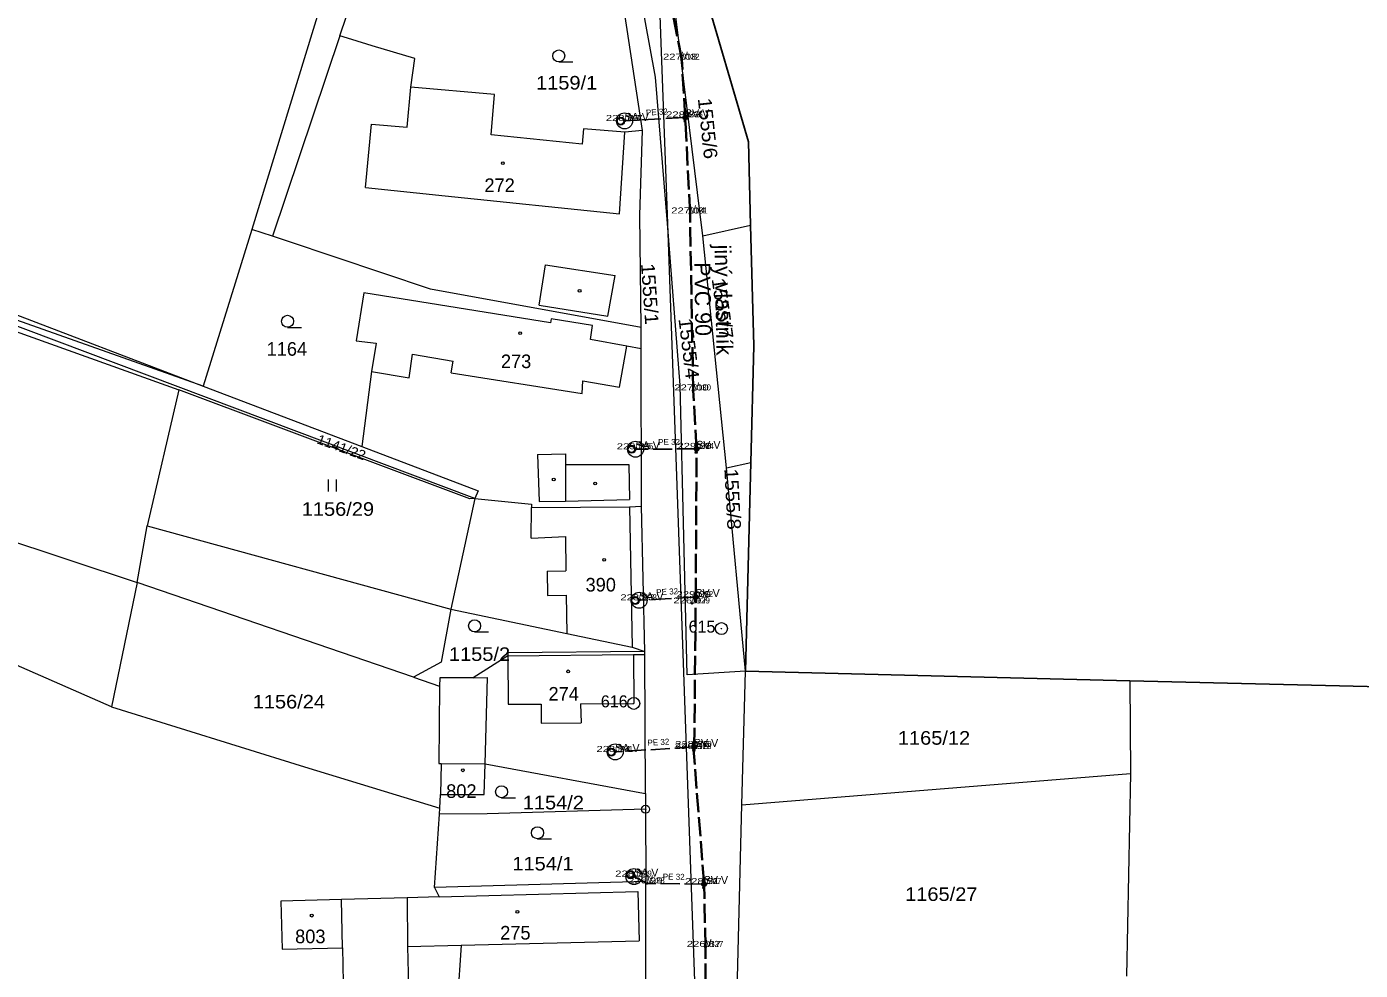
# Model space of a CAD drawing. Extents: x -686207 to -681951, y -1020493 to -1017811.
# Drawn here: x -684335.4 to -684168.7, y -1019065.6 to -1018947.7 of the extents above; entities that cross this region are included whole.
import ezdxf
from ezdxf.enums import TextEntityAlignment as Align

# ---------------------------------------------------------------- set-up
doc = ezdxf.new("R2010")
doc.units = 0
doc.header["$LTSCALE"] = 0.4
doc.header["$PDMODE"] = 32
doc.header["$PDSIZE"] = 0.2
doc.linetypes.add('DOTTED', pattern=[1.5, 0.3, -1.2])
doc.linetypes.add('LONG_DASHED', pattern=[7.5, 6, -1.5])
for name, color, linetype, lineweight in [('1', 7, 'Continuous', 13), ('10', 7, 'Continuous', 13), ('12', 7, 'Continuous', 13), ('24', 7, 'Continuous', 25), ('3', 7, 'Continuous', 13), ('35', 7, 'LONG_DASHED', 35), ('4', 7, 'Continuous', 13), ('5', 7, 'Continuous', 13), ('50', 7, 'LONG_DASHED', 25), ('51', 7, 'DOTTED', 25), ('8', 7, 'Continuous', 13)]:
    doc.layers.add(name, color=color, linetype=linetype, lineweight=lineweight)
for name, color, linetype in [('17', 7, 'Continuous'), ('19', 7, 'Continuous'), ('2', 7, 'Continuous')]:
    doc.layers.add(name, color=color, linetype=linetype)

msp = doc.modelspace()

# ---------------------------------------------------------------- linework, layer by layer
at = {"layer": '1'}
for p, q in [((-684296.2, -1018948.84), (-684293.13, -1018939.72)), ((-684250.83, -1018973.82), (-684254.58, -1018943.22)), ((-684258.39, -1018960.65), (-684260.58, -1018946.11)), ((-684296.2, -1018948.84), (-684304.64, -1018973.88)), ((-684396.43, -1018960.78), (-684313.29, -1018992.62)), ((-684397.4, -1018964.07), (-684316.33, -1018993.06)), ((-684279.34, -1019006.65), (-684370.61, -1018972.34)), ((-684250.83, -1018973.82), (-684244.86, -1018972.48)), ((-684247.88, -1019002.83), (-684250.83, -1018973.82)), ((-684284.86, -1018980.48), (-684302.74, -1018974.51)), ((-684258.55, -1018985.3), (-684284.86, -1018980.48)), ((-684258.55, -1018987.93), (-684258.55, -1018985.3)), ((-684258.49, -1019007.63), (-684258.55, -1018987.93)), ((-684313.29, -1018992.62), (-684293.45, -1019000.15)), ((-684247.88, -1019002.83), (-684244.85, -1019002.17)), ((-684244.85, -1019002.17), (-684245.52, -1019028.24)), ((-684245.52, -1019028.24), (-684247.88, -1019002.83)), ((-684279.34, -1019006.65), (-684282.34, -1019020.47)), ((-684258.07, -1019025.76), (-684258.49, -1019007.63)), ((-684275.21, -1019026.33), (-684279.56, -1019029.05)), ((-684245.95, -1019044.93), (-684245.52, -1019028.24)), ((-684197.45, -1019029.43), (-684245.52, -1019028.24)), ((-684197.45, -1019029.43), (-684197.36, -1019041.02)), ((-684160.81, -1019030.34), (-684197.45, -1019029.43)), ((-684283.55, -1019039.78), (-684283.61, -1019043.67)), ((-684283.55, -1019039.78), (-684278.06, -1019039.83)), ((-684245.95, -1019044.93), (-684197.36, -1019041.02)), ((-684197.36, -1019041.02), (-684197.86, -1019066.35)), ((-684283.72, -1019045.37), (-684283.61, -1019043.67)), ((-684258.01, -1019043.53), (-684258, -1019045.5)), ((-684283.77, -1019046.13), (-684283.72, -1019045.37)), ((-684258, -1019045.5), (-684257.97, -1019054.54)), ((-684246.54, -1019068.23), (-684245.95, -1019044.93)), ((-684284.36, -1019055.26), (-684283.77, -1019046.13)), ((-684257.97, -1019054.54), (-684284.36, -1019055.26)), ((-684295.88, -1019062.8), (-684296.01, -1019056.79)), ((-684281.03, -1019062.49), (-684282.28, -1019080.53)), ((-684295.88, -1019062.8), (-684295.43, -1019083.6))]:
    msp.add_line(p, q, dxfattribs=at)
for points in [[(-684352.04, -1018881.31), (-684348.33, -1018883.78), (-684304.05, -1018913.23), (-684290.12, -1018917.3), (-684307.2, -1018973.02)], [(-684245.52, -1019028.24), (-684252.8, -1019028.7), (-684253.19, -1019011.4), (-684253.65, -1018992.5), (-684255.27, -1018972.28), (-684256.74, -1018953.99), (-684259.43, -1018939.35), (-684263.91, -1018924.31), (-684269.41, -1018905.26)], [(-684244.86, -1018972.48), (-684245.12, -1018962.07), (-684250.92, -1018942.27)], [(-684258.39, -1018960.65), (-684260.59, -1018960.86), (-684265.76, -1018960.44), (-684265.92, -1018962.38), (-684277.31, -1018961.21), (-684276.86, -1018956.17), (-684287.35, -1018955.23), (-684286.84, -1018951.67), (-684292.17, -1018950.06), (-684294.7, -1018949.29), (-684296.2, -1018948.84)], [(-684258.55, -1018985.3), (-684258.71, -1018971.23), (-684258.39, -1018960.65)], [(-684307.2, -1018973.02), (-684313.29, -1018992.62), (-684370.61, -1018972.34)], [(-684244.85, -1019002.17), (-684244.48, -1018987.59), (-684244.86, -1018972.48)], [(-684302.74, -1018974.51), (-684304.64, -1018973.88), (-684307.2, -1018973.02)], [(-684258.55, -1018987.93), (-684260.33, -1018987.61), (-684264.89, -1018986.78), (-684264.63, -1018985.03), (-684269.78, -1018984.2), (-684269.86, -1018984.69), (-684293.19, -1018980.93), (-684294.16, -1018986.96), (-684291.66, -1018987.22), (-684292.25, -1018990.79), (-684293.45, -1019000.15)], [(-684324.74, -1019032.69), (-684354.34, -1019019.74), (-684372.98, -1019010.9), (-684378.92, -1019008.36), (-684382.62, -1019006.2), (-684396.96, -1018997.84), (-684406.29, -1018992.65)], [(-684316.33, -1018993.06), (-684320.3, -1019010.06), (-684282.34, -1019020.47)], [(-684279.34, -1019006.65), (-684279.98, -1019006.68), (-684316.33, -1018993.06)], [(-684293.45, -1019000.15), (-684278.91, -1019005.68), (-684279.34, -1019006.65)], [(-684279.34, -1019006.65), (-684272.27, -1019007.35), (-684272.27, -1019007.78), (-684259.99, -1019007.68), (-684258.49, -1019007.63)], [(-684287.01, -1019028.99), (-684321.55, -1019017.15), (-684324.74, -1019032.69)], [(-684282.34, -1019020.47), (-684283.55, -1019027.1), (-684287.01, -1019028.99), (-684283.75, -1019030.11)], [(-684282.34, -1019020.47), (-684267.85, -1019023.51), (-684259.68, -1019025.25), (-684258.07, -1019025.76)], [(-684258.07, -1019025.76), (-684275.21, -1019025.93), (-684275.21, -1019026.33)], [(-684258.01, -1019043.53), (-684258.07, -1019026.15), (-684258.07, -1019025.76)], [(-684279.56, -1019029.05), (-684283.73, -1019029.09), (-684283.75, -1019030.11)], [(-684283.75, -1019030.11), (-684283.85, -1019039.77), (-684283.55, -1019039.78)], [(-684324.74, -1019032.69), (-684300.63, -1019040.2), (-684285.21, -1019044.91), (-684283.72, -1019045.37)], [(-684283.61, -1019043.67), (-684278.17, -1019043.67), (-684278.06, -1019039.83)], [(-684278.06, -1019039.83), (-684258.26, -1019043.49), (-684258.01, -1019043.53)], [(-684258, -1019045.5), (-684277.81, -1019046.06), (-684283.77, -1019046.13)], [(-684284.36, -1019055.26), (-684283.79, -1019056.46), (-684287.78, -1019056.57), (-684296.01, -1019056.79)], [(-684257.93, -1019070.84), (-684257.94, -1019066.54), (-684257.97, -1019054.54)], [(-684296.01, -1019056.79), (-684303.59, -1019056.99), (-684303.43, -1019062.98), (-684295.88, -1019062.8)], [(-684287.78, -1019056.57), (-684287.75, -1019062.66), (-684281.03, -1019062.49)]]:
    msp.add_lwpolyline(points, dxfattribs=at)
for p in [(-684253.47, -1018951.8), (-684260.62, -1018959.46), (-684253.08, -1018959.02), (-684252.44, -1018971.03), (-684252.05, -1018993.15), (-684259.25, -1019000.5), (-684251.67, -1019000.45), (-684258.8, -1019019.38), (-684251.77, -1019018.98), (-684252.18, -1019019.77), (-684251.96, -1019037.71), (-684261.79, -1019038.33), (-684252, -1019037.97), (-684259.44, -1019053.91), (-684257.83, -1019054.77), (-684250.73, -1019054.85), (-684250.5, -1019062.7)]:
    msp.add_point(p, dxfattribs=at)
at = {"layer": '10'}
for points in [[(-684252.93, -1018959.52), (-684253.23, -1018958.52), (-684252.93, -1018958.52), (-684253.23, -1018959.52)], [(-684251.52, -1019000.95), (-684251.82, -1018999.95), (-684251.52, -1018999.95), (-684251.82, -1019000.95)], [(-684251.62, -1019019.48), (-684251.92, -1019018.48), (-684251.62, -1019018.48), (-684251.92, -1019019.48)], [(-684251.81, -1019038.21), (-684252.11, -1019037.21), (-684251.81, -1019037.21), (-684252.11, -1019038.21)], [(-684250.58, -1019055.35), (-684250.88, -1019054.35), (-684250.58, -1019054.35), (-684250.88, -1019055.35)]]:
    msp.add_lwpolyline(points, close=True, dxfattribs=at)
for centre in [(-684260.62, -1018959.46), (-684259.25, -1019000.5), (-684258.8, -1019019.38), (-684261.79, -1019038.33), (-684259.44, -1019053.91)]:
    msp.add_circle(centre, 1, dxfattribs=at)
at = {"layer": '12'}
for centre, radius in [((-684261.119, -1018959.489), 0.5), ((-684261.119, -1018959.489), 0.4), ((-684253.03, -1018959.017), 0.3), ((-684253.03, -1018959.017), 0.2), ((-684253.03, -1018959.017), 0.1), ((-684259.75, -1019000.503), 0.5), ((-684259.75, -1019000.503), 0.4), ((-684251.62, -1019000.45), 0.3), ((-684251.62, -1019000.45), 0.2), ((-684251.62, -1019000.45), 0.1), ((-684259.299, -1019019.408), 0.5), ((-684259.299, -1019019.408), 0.4), ((-684251.72, -1019018.977), 0.3), ((-684251.72, -1019018.977), 0.2), ((-684251.72, -1019018.977), 0.1), ((-684251.91, -1019037.707), 0.3), ((-684251.91, -1019037.707), 0.2), ((-684251.91, -1019037.707), 0.1), ((-684262.289, -1019038.361), 0.5), ((-684262.289, -1019038.361), 0.4), ((-684259.881, -1019053.674), 0.5), ((-684259.881, -1019053.674), 0.4), ((-684250.68, -1019054.851), 0.3), ((-684250.68, -1019054.851), 0.2), ((-684250.68, -1019054.851), 0.1)]:
    msp.add_circle(centre, radius, dxfattribs=at)
at = {"layer": '24'}
msp.add_lwpolyline([(-684160.81, -1019030.34), (-684197.45, -1019029.43), (-684245.52, -1019028.24), (-684244.85, -1019002.17), (-684244.48, -1018987.59), (-684244.86, -1018972.48), (-684245.12, -1018962.07), (-684250.92, -1018942.27), (-684254.05, -1018931.3), (-684260.28, -1018911.63), (-684262.13, -1018906.6), (-684266.84, -1018905.73), (-684269.41, -1018905.26), (-684271.8, -1018904.82), (-684308.9, -1018882.43), (-684318.89, -1018898.69), (-684349.29, -1018877.65)], dxfattribs=at)
at = {"layer": '3'}
for p, q in [((-684268.843, -1018952.09), (-684267.093, -1018952.09)), ((-684302.743, -1018985.26), (-684300.993, -1018985.26)), ((-684297.641, -1019005.77), (-684297.641, -1019004.27)), ((-684296.64, -1019005.77), (-684296.64, -1019004.27)), ((-684279.363, -1019023.32), (-684277.613, -1019023.32)), ((-684275.993, -1019044.05), (-684274.243, -1019044.05)), ((-684271.503, -1019049.19), (-684269.753, -1019049.19))]:
    msp.add_line(p, q, dxfattribs=at)
for centre in [(-684268.8429, -1018951.3398), (-684302.7429, -1018984.5098), (-684279.3629, -1019022.5698), (-684275.9929, -1019043.2998), (-684271.5029, -1019048.4398)]:
    msp.add_circle(centre, 0.75, dxfattribs=at)
at = {"layer": '35'}
for p, q in [((-684251.72, -1019018.977), (-684251.62, -1019000.45)), ((-684251.91, -1019037.707), (-684251.72, -1019018.977))]:
    msp.add_line(p, q, dxfattribs=at)
for points in [[(-684253.03, -1018959.017), (-684253.47, -1018951.8), (-684256.7, -1018935.51), (-684259.884, -1018921.811)], [(-684251.62, -1019000.45), (-684252.05, -1018993.15), (-684252.44, -1018971.03), (-684253.03, -1018959.017)], [(-684250.68, -1019054.851), (-684252, -1019037.97), (-684251.91, -1019037.707)], [(-684250.52, -1019082.188), (-684250.5, -1019062.7), (-684250.68, -1019054.851)]]:
    msp.add_lwpolyline(points, dxfattribs=at)
at = {"layer": '4'}
for p, q in [((-684256.44, -1018939.82), (-684255.27, -1018972.28)), ((-684287.8, -1018960.23), (-684287.35, -1018955.23)), ((-684293.01, -1018967.79), (-684292.27, -1018959.86)), ((-684292.27, -1018959.86), (-684287.8, -1018960.23)), ((-684261.27, -1018971.07), (-684260.59, -1018960.86)), ((-684293.01, -1018967.79), (-684283.06, -1018968.82)), ((-684283.06, -1018968.82), (-684261.27, -1018971.07)), ((-684255.27, -1018972.28), (-684250.96, -1019092.18)), ((-684271.3, -1018982.5), (-684270.5, -1018977.43)), ((-684270.5, -1018977.43), (-684261.81, -1018978.8)), ((-684262.7, -1018983.87), (-684261.81, -1018978.8)), ((-684271.3, -1018982.5), (-684262.7, -1018983.87)), ((-684261.26, -1018992.75), (-684260.33, -1018987.61)), ((-684287.53, -1018991.57), (-684287.12, -1018988.6)), ((-684287.12, -1018988.6), (-684282.06, -1018989.49)), ((-684292.25, -1018990.79), (-684287.53, -1018991.57)), ((-684282.29, -1018990.93), (-684282.06, -1018989.49)), ((-684282.29, -1018990.93), (-684265.93, -1018993.53)), ((-684265.93, -1018993.53), (-684265.82, -1018991.93)), ((-684265.82, -1018991.93), (-684261.26, -1018992.75)), ((-684372.72, -1019000.15), (-684321.55, -1019017.15)), ((-684271.51, -1019001.17), (-684271.29, -1019007.04)), ((-684267.99, -1019002.42), (-684267.99, -1019006.97)), ((-684260.09, -1019002.39), (-684259.99, -1019006.79)), ((-684271.29, -1019007.04), (-684267.99, -1019006.97)), ((-684267.99, -1019006.97), (-684259.99, -1019006.79)), ((-684259.99, -1019007.68), (-684259.68, -1019025.25)), ((-684272.3, -1019011.63), (-684272.27, -1019007.78)), ((-684321.55, -1019017.15), (-684320.3, -1019010.06)), ((-684272.3, -1019011.63), (-684268.01, -1019011.42)), ((-684268.01, -1019011.42), (-684267.95, -1019015.69)), ((-684270.29, -1019015.72), (-684267.95, -1019015.69)), ((-684270.29, -1019015.72), (-684270.25, -1019018.77)), ((-684270.25, -1019018.77), (-684267.91, -1019018.74)), ((-684267.91, -1019018.74), (-684267.85, -1019023.51)), ((-684275.21, -1019026.33), (-684259.52, -1019026.16)), ((-684275.21, -1019026.33), (-684275.16, -1019032.38)), ((-684259.52, -1019026.16), (-684258.07, -1019026.15)), ((-684259.52, -1019026.16), (-684259.48, -1019032.26)), ((-684279.56, -1019029.05), (-684277.75, -1019029.04)), ((-684278.06, -1019039.83), (-684277.75, -1019029.04)), ((-684266.13, -1019032.31), (-684259.48, -1019032.26)), ((-684266.13, -1019032.31), (-684266.06, -1019034.71)), ((-684283.79, -1019056.46), (-684258.94, -1019055.79)), ((-684258.94, -1019055.79), (-684258.8, -1019061.93)), ((-684287.75, -1019062.66), (-684287.21, -1019083.44)), ((-684281.03, -1019062.49), (-684258.8, -1019061.93))]:
    msp.add_line(p, q, dxfattribs=at)
for points in [[(-684271.51, -1019001.17), (-684268, -1019001.08), (-684267.99, -1019002.42), (-684260.09, -1019002.39)], [(-684275.16, -1019032.38), (-684271.04, -1019032.35), (-684271.03, -1019034.73), (-684266.06, -1019034.71)]]:
    msp.add_lwpolyline(points, dxfattribs=at)
at = {"layer": '5'}
for centre in [(-684275.8468, -1018964.7492), (-684266.2368, -1018980.7092), (-684273.6668, -1018985.9892), (-684269.4768, -1019004.2692), (-684264.2968, -1019004.7792), (-684263.1668, -1019014.3192), (-684267.6768, -1019028.2592), (-684280.8468, -1019040.6292), (-684299.7268, -1019058.7892), (-684274.0168, -1019058.3192)]:
    msp.add_circle(centre, 0.175, dxfattribs=at)
at = {"layer": '50'}
for p, q in [((-684253.08, -1018959.02), (-684260.62, -1018959.46)), ((-684253.03, -1018959.017), (-684253.08, -1018959.02)), ((-684251.67, -1019000.45), (-684259.25, -1019000.5)), ((-684251.62, -1019000.45), (-684251.67, -1019000.45)), ((-684251.96, -1019037.71), (-684261.79, -1019038.33)), ((-684251.91, -1019037.707), (-684251.96, -1019037.71)), ((-684250.68, -1019054.851), (-684250.73, -1019054.85))]:
    msp.add_line(p, q, dxfattribs=at)
for points in [[(-684251.72, -1019018.977), (-684251.77, -1019018.98), (-684258.8, -1019019.38)], [(-684250.73, -1019054.85), (-684257.83, -1019054.77), (-684259.44, -1019053.91)]]:
    msp.add_lwpolyline(points, dxfattribs=at)
at = {"layer": '51'}
for p, q in [((-684260.62, -1018959.46), (-684261.119, -1018959.489)), ((-684259.25, -1019000.5), (-684259.75, -1019000.503)), ((-684258.8, -1019019.38), (-684259.299, -1019019.408)), ((-684261.79, -1019038.33), (-684262.289, -1019038.361)), ((-684259.44, -1019053.91), (-684259.881, -1019053.674))]:
    msp.add_line(p, q, dxfattribs=at)
at = {"layer": '8'}
for centre, radius in [((-684248.51, -1019022.9198), 0.75), ((-684248.51, -1019022.9198), 0.03), ((-684259.48, -1019032.2598), 0.75), ((-684259.48, -1019032.2598), 0.03), ((-684258, -1019045.4999), 0.5), ((-684258, -1019045.4999), 0.0303)]:
    msp.add_circle(centre, radius, dxfattribs=at)

# ---------------------------------------------------------------- texts
at = {"layer": '17'}
for s, p in [('jiný vlastník', (-684249.2491, -1018981.8544)), ('PVC 90', (-684251.8377, -1018981.7474))]:
    msp.add_text(s, height=2, rotation=271.01, dxfattribs=at).set_placement(p, align=Align.CENTER)
at = {"layer": '19'}
for rotation, p in [(3.34, (-684256.5638, -1018958.7221)), (0.378, (-684255.052, -1018999.9717)), (3.257, (-684255.2778, -1019018.6791)), (3.609, (-684256.3666, -1019037.4875)), (359.354, (-684254.4777, -1019054.3078))]:
    msp.add_text('PE 32', height=0.75, rotation=rotation, dxfattribs=at).set_placement(p, align=Align.CENTER)
at = {"layer": '2'}
for s, height, p in [('0132', 0.75, (-684253.47, -1018951.8)), ('0237', 0.75, (-684260.62, -1018959.46)), ('0236', 0.75, (-684253.08, -1018959.02)), ('272', 1.7, (-684278.134, -1018968.35)), ('0131', 0.75, (-684252.44, -1018971.03)), ('1164', 1.7, (-684305.357, -1018988.809)), ('273', 1.7, (-684276.074, -1018990.36)), ('0130', 0.75, (-684252.05, -1018993.15)), ('0235', 0.75, (-684259.25, -1019000.5)), ('0234', 0.75, (-684251.67, -1019000.45)), ('390', 1.7, (-684265.494, -1019018.28)), ('0233', 0.75, (-684258.8, -1019019.38)), ('0129', 0.75, (-684252.18, -1019019.77)), ('0232', 0.75, (-684251.77, -1019018.98)), ('274', 1.7, (-684270.124, -1019031.919)), ('0231', 0.75, (-684261.79, -1019038.33)), ('0128', 0.75, (-684252, -1019037.97)), ('0230', 0.75, (-684251.96, -1019037.71)), ('802', 1.7, (-684282.914, -1019044.08)), ('0229', 0.75, (-684259.44, -1019053.91)), ('0228', 0.75, (-684257.83, -1019054.77)), ('0227', 0.75, (-684250.73, -1019054.85)), ('803', 1.7, (-684301.794, -1019062.24)), ('275', 1.7, (-684276.164, -1019061.78)), ('0127', 0.75, (-684250.5, -1019062.7))]:
    msp.add_text(s, height=height, dxfattribs=at).set_placement(p)
at = {"layer": '2', "width": 1.1}
for s, p in [('1159/1', (-684271.685, -1018955.539)), ('1156/29', (-684300.97, -1019008.82)), ('1155/2', (-684282.575, -1019026.96)), ('1156/24', (-684307.1, -1019032.9)), ('1165/12', (-684226.46, -1019037.429)), ('1154/2', (-684273.345, -1019045.51)), ('1154/1', (-684274.645, -1019053.15)), ('1165/27', (-684225.548, -1019056.96))]:
    msp.add_text(s, height=1.7, dxfattribs=at).set_placement(p)
for s, height, rotation, p in [('1555/6', 1.7, 276, (-684251.465, -1018956.678)), ('1555/1', 1.7, 274, (-684258.568, -1018977.331)), ('1555/7', 1.7, 278, (-684249.741, -1018979.218)), ('1555/4', 1.7, 277, (-684253.883, -1018984.203)), ('1141/22', 1.19, 340, (-684299.183, -1018999.729)), ('1555/8', 1.7, 273, (-684248.148, -1019002.954))]:
    msp.add_text(s, height=height, rotation=rotation, dxfattribs=at).set_placement(p)
at = {"layer": '3', "width": 1.4}
for s, p in [('227 08 ', (-684253.47, -1018951.8)), ('228 83 ', (-684260.62, -1018959.46)), ('228 83 ', (-684253.08, -1018959.02)), ('227 04 ', (-684252.44, -1018971.03)), ('227 00 ', (-684252.05, -1018993.15)), ('229 35 ', (-684259.25, -1019000.5)), ('229 08 ', (-684251.67, -1019000.45)), ('228 93 ', (-684258.8, -1019019.38)), ('226 97 ', (-684252.18, -1019019.77)), ('229 09 ', (-684251.77, -1019018.98)), ('228 74 ', (-684261.79, -1019038.33)), ('226 90 ', (-684252, -1019037.97)), ('228 76 ', (-684251.96, -1019037.71)), ('228 71 ', (-684259.44, -1019053.91)), ('226 99 ', (-684257.83, -1019054.77)), ('228 51 ', (-684250.73, -1019054.85)), ('226 87 ', (-684250.5, -1019062.7))]:
    msp.add_text(s, height=0.75, dxfattribs=at).set_placement(p, align=Align.CENTER)
at = {"layer": '4', "width": 0.85}
for p in [(-684253.47, -1018951.8), (-684252.44, -1018971.03), (-684252.05, -1018993.15), (-684252.18, -1019019.77), (-684252, -1019037.97), (-684257.83, -1019054.77), (-684250.5, -1019062.7)]:
    msp.add_text('V', height=1, dxfattribs=at).set_placement(p)
at = {"layer": '4'}
for s, p in [('SA V', (-684260.62, -1018959.46)), ('SV V', (-684253.08, -1018959.02)), ('SA V', (-684259.25, -1019000.5)), ('SV V', (-684251.67, -1019000.45)), ('SA V', (-684258.8, -1019019.38)), ('SV V', (-684251.77, -1019018.98)), ('SA V', (-684261.79, -1019038.33)), ('SV V', (-684251.96, -1019037.71)), ('SA V', (-684259.44, -1019053.91)), ('SV V', (-684250.73, -1019054.85))]:
    msp.add_text(s, height=1, dxfattribs=at).set_placement(p)
at = {"layer": '8'}
for s, p in [('615', (-684252.613, -1019023.42)), ('616', (-684263.583, -1019032.76))]:
    msp.add_text(s, height=1.5, dxfattribs=at).set_placement(p)

doc.saveas('drawing.dxf')
